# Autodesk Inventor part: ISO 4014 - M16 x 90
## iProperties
Comments: To add or edit properties for Autodesk Inventor files, use iProperties.
Created: 2004-01
Part Number: ISO 4014 - M16 x 90
Vendor: Autodesk Inc.
Document SubType Name: Modeling
Designer: Administratör
Material: Standard
Description: Sexkantskruv
Standard: ISO 4014
Alert: To add or edit properties for Autodesk Inventor files, use iProperties.
Control State: 0
Master: False
Checked Out: False
Shininess: 64.0
Length Units: 11269
Angle Units: 11279
Time Units: 11290
Mass Units: 11283
Length Display Precision: 3
Angle Display Precision: 2
Compacted: True
EGR: 1
Density: 0.0
Volumn: 0.0
Area: 0.0
PropertySet Name: Model Information
Author: Administratör
Revision Number: 8
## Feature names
1. Kropp [Revolution]
2. Huvud [Extrusion]
3. Fas1 [Revolution]
4. Fas2 [Chamfer]
